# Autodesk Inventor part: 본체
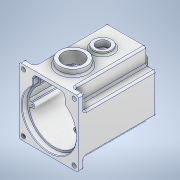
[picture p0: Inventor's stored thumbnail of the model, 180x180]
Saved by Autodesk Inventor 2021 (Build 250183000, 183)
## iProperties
Created: 2022-08
Part Number: 본체
Material: 알루미늄 6061
Document SubType Name: Modeling
Designer: Owner
Mass: 1404.24 g
Surface Area: 1170.95 cm^2
Volume: 520.089 cm^3
Density: 2.7 g/cm^3
Appearance: 알루미늄 - 평지
Author: Owner
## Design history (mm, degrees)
sketch "스케치1"
  geometry: L1 (-49, 55)-(49, 55); L2 (49, 55)-(49, -55); L3 (49, -55)-(-49, -55); L4 (-49, -55)-(-49, 55); L5 (-49, 55)-(49, -55); L6 (49, 55)-(-49, -55); 1 further point
  constraints: 12 end point, 2 midpoint, 2 parallel, 1 horizontal, 1 perpendicular
  dimensions: "d0" = 98 distance of L2.end L3.end; "d1" = 110 distance of L1.end L2.end
extrude "돌출1" new body sketch "스케치1" distance "d2" = 130; taper "d3" = 0 deg
sketch "스케치4"
  geometry: L1 (49, 55)-(-49, 55) reference; L2 (33, 55)-(49, 55); L3 (49, 55)-(49, 28); L4 (49, 28)-(33, 28); L5 (33, 28)-(33, 55); L6 (-49, -55)-(49, -55) reference; L7 (33, -38)-(49, -38); L8 (49, -38)-(49, -55); L9 (49, -55)-(33, -55); L10 (33, -55)-(33, -38); L11 (49, -55)-(49, 55) reference; 4 further points
  constraints: 16 end point, 4 parallel, 2 horizontal, 2 perpendicular, 2 point on line, 1 midpoint
  dimensions: "d9" = 16 distance of L3.end L4.end; "d10" = 16 distance of L7.start L7.end; "d11" = 27 distance of L4.end L2.start; "d12" = 17 distance of L9.end L7.start
extrude "돌출2" cut sketch "스케치4" distance "d13" = 120; taper "d14" = 0 deg
sketch "스케치5"
  geometry: L1 (-49, -55)-(49, -55) reference; L2 (-20, 48)-(20, 48); L3 (26, 42)-(26, 33.249); L4 (-26, 33.249)-(-26, 42); A1 r 45 centre (0, -5) between (-27.188, 30.859) and (27.188, 30.859); A2 r 3 centre (-29, 33.249) between (-27.188, 30.859) and (-26, 33.249); A3 r 3 centre (29, 33.249) between (26, 33.249) and (27.188, 30.859); A4 r 6 centre (-20, 42) between (-20, 48) and (-26, 42); A5 r 6 centre (20, 42) between (26, 42) and (20, 48); 5 further points
  constraints: 12 point on circle, 8 tangent, 6 end point, 6 point on line, 5 centre point, 2 equal radius, 1 horizontal, 1 parallel, 1 perpendicular, 1 vertical alignment
  dimensions: "d15" = 50 distance from line of A1.centre L1; "d16" = 45 radius of A1; "d17" = 52 distance between parallel lines of L3 L4; "d18" = 26 distance from line of A1.centre L3; "d19" = 53 distance from line of L2 A1.centre; "d20" = 3 radius of A2; "d23" = 6 radius of A4
extrude "돌출3" cut sketch "스케치5" distance "d21" = 9; taper "d22" = 0 deg
fillet "모깎기1" dims "d24" = 3
fillet "모깎기2" dims "d25" = 3
fillet "모깎기3" dims "d26" = 3
fillet "모깎기4" dims "d27" = 3
fillet "모깎기5" dims "d28" = 3
sketch "스케치6"
  geometry: L1 (-27, 33)-(27, 33); L2 (27, 33)-(27, -21); L3 (27, -21)-(-27, -21); L4 (-27, -21)-(-27, 33); L5 (-27, 33)-(27, -21); L6 (27, 33)-(-27, -21); L7 (-30, -55)-(30, -55) reference; 3 further points
  constraints: 12 end point, 4 midpoint, 2 parallel, 1 horizontal, 1 perpendicular, 1 vertical alignment
  dimensions: "d29" = 54 distance of L2.end L3.end; "d30" = 54 distance of L1.end L2.end; "d109" = 61 distance from line of point (0, 6) L7
extrude "돌출4" join sketch "스케치6" distance "d31" = 7; taper "d32" = 0 deg
fillet "모깎기6" dims "d33" = 3
fillet "모깎기7" dims "d34" = 3
sketch "스케치7"
  geometry: L1 (27, -18)-(27, 30) reference; L2 (24, 33)-(-24, 33) reference; 2 further points
  constraints: 1 coincident
  dimensions: "d110" = 27 distance from line of point (0, 6) L1; "d111" = 27 distance from line of point (0, 6) L2
hole "구멍1" sketch "스케치7" at (0, 6) diameter "d35" = 32; stored, may be unused: countersink angle "d39" = 90 deg, drill point angle "d41" = 0 deg; dims "d36" = 8, "d37" = 4, "d38" = 2, "d40" = 8.3
chamfer "모따기1" distance "d42" = 0.8; stored, may be unused: second distance "d43" = 2, angle "d44" = 30 deg
sketch "스케치8"
  geometry: L1 (92, 0)-(0, 0) reference; C1 r 15 at (46, 89); 2 further points
  constraints: 1 centre point, 1 midpoint, 1 vertical alignment
  dimensions: "d45" = 30 diameter of C1; "d46" = 89 distance from line of C1.centre L1
extrude "돌출5" join sketch "스케치8" distance "d47" = 5; taper "d48" = 0 deg
sketch "스케치9"
  geometry: L1 (92, 0)-(0, 0) reference; C1 r 22.5 at (46, 40); C2 r 15 at (46, 89) reference; 1 further point
  constraints: 1 centre point, 1 vertical alignment
  dimensions: "d49" = 45 diameter of C1; "d50" = 40 distance from line of C1.centre L1
extrude "돌출6" join sketch "스케치9" distance "d51" = 10; taper "d52" = 0 deg
fillet "모깎기8" dims "d53" = 3
sketch "스케치10"
  geometry: L1 (49, -52)-(49, 52) reference; L2 (-46, -55)-(46, -55) reference; 5 further points
  constraints: 2 horizontal alignment, 2 vertical alignment
  dimensions: "d54" = 7 distance from line of point (42, -48) L1; "d55" = 7 distance from line of point (42, -48) L2; "d56" = 96 distance of point (42, 48) point (42, -48); "d57" = 84 distance of point (-42, -48) point (42, -48)
hole "구멍2" sketch "스케치10" at (42, -48), (-42, -48), (-42, 48), (42, 48) diameter "d58" = 7; stored, may be unused: countersink angle "d62" = 90 deg, drill point angle "d64" = 0 deg; dims "d59" = 8, "d60" = 4, "d61" = 2, "d63" = 10
sketch "스케치11"
  geometry: L1 (-130, 104)-(-130, 83) reference; L2 (-13, 107)-(-127, 107) reference; 2 further points
  constraints: 1 other
  dimensions: "d65" = 65 distance from line of point (-65, 47) L1; "d66" = 60 distance from line of point (-65, 47) L2
feature "엠보싱1" sketch "스케치11" dims "d9" = 16, "d11" = 27, "d67" = 0.5, "d68" = 0
sketch "스케치13"
  geometry: C1 r 16 at (0, 0) reference; 2 further points
  constraints: 1 coincident
hole "구멍3" sketch "스케치13" at (0, 0) diameter "d71" = 28; stored, may be unused: countersink angle "d75" = 90 deg, drill point angle "d77" = 0 deg; dims "d72" = 8, "d73" = 4, "d74" = 2, "d76" = 10
fillet "모깎기9" dims "d78" = 0.3
sketch "스케치14"
  geometry: L1 (-20, 48)-(20, 48) reference; L2 (-26, 33.249)-(-26, 42) reference; L3 (26, 42)-(26, 33.249) reference; L4 (-23, 33.249)-(-23, 42); L5 (-20, 45)-(20, 45); L6 (23, 42)-(23, 33.249); L7 (-70.297, -5)-(83.266, -5); L8 (-46, -55)-(46, -55) reference; L9 (35.777, -1)-(41.809, -1); L10 (-41.809, -1)-(-35.777, -1); L11 (-41.809, -9)-(-35.777, -9); L12 (35.777, -9)-(41.809, -9); C1 r 14 at (0, 6) reference; A1 r 6 centre (-20, 42) between (-20, 48) and (-26, 42) reference; A2 r 3 centre (-29, 33.249) between (-27.188, 30.859) and (-26, 33.249) reference; A3 r 45 centre (0, -5) between (-27.188, 30.859) and (27.188, 30.859) reference; A4 r 3 centre (29, 33.249) between (26, 33.249) and (27.188, 30.859) reference; A5 r 6 centre (20, 42) between (26, 42) and (20, 48) reference; A6 r 6 centre (-29, 33.249) between (-25.375, 28.468) and (-23, 33.249); A7 r 3 centre (-20, 42) between (-20, 45) and (-23, 42); A8 r 3 centre (20, 42) between (23, 42) and (20, 45); A9 r 6 centre (29, 33.249) between (23, 33.249) and (25.375, 28.468); A10 r 36 centre (0, -5) between (-36, -5) and (36, -5); A11 r 4 centre (-36, -5) between (-36, -9) and (-36, -1); A12 r 4 centre (36, -5) between (36, -1) and (36, -9); A13 r 42 centre (0, -5) between (-25.375, 28.468) and (-41.809, -1); A14 r 42 centre (0, -5) between (-41.809, -9) and (41.809, -9); A15 r 42 centre (0, -5) between (41.809, -1) and (25.375, 28.468); 1 further point
  constraints: 24 point on circle, 16 end point, 10 centre point, 6 point on line, 5 horizontal, 4 tangent, 1 coincident, 6 other
  dimensions: "d89" = 50 distance between parallel lines of L7 L8; "d90" = 72 diameter of A10; "d91" = 8 diameter of A11; "d92" = 8 diameter of A12; "d93" = 42 radius of A15; "d94" = 42 radius of A14; "d95" = 42 radius of A13; "d96" = 6 radius of A6
extrude "돌출7" cut sketch "스케치14" distance "d80" = 112; taper "d81" = 0 deg
fillet "모깎기10" dims "d97" = 3
fillet "모깎기11" dims "d98" = 3
chamfer "모따기2" distance "d99" = 1; stored, may be unused: second distance "d100" = 2, angle "d101" = 30 deg
sketch "스케치16"
  geometry: A1 r 4 centre (-36, -5) between (-36, -9) and (-36, -1) reference; A2 r 4 centre (36, -5) between (36, -1) and (36, -9) reference; 3 further points
  constraints: 2 coincident
hole "구멍5" sketch "스케치16" at (-36, -5), (36, -5) diameter "d102" = 3.242; stored, may be unused: countersink angle "d106" = 90 deg, drill point angle "d108" = 118 deg; dims "d103" = 7, "d104" = 4, "d105" = 2, "d107" = 9
sketch "스케치17"
  geometry: C1 r 15 at (23, -80) reference; 1 further point
hole "구멍6" sketch "스케치17" at (23, -80) diameter "d112" = 20; stored, may be unused: countersink angle "d116" = 90 deg, drill point angle "d118" = 0 deg; dims "d113" = 7, "d114" = 30, "d115" = 5, "d117" = 20
sketch "스케치18"
  geometry: C1 r 22.5 at (0, 0) reference; 2 further points
  constraints: 1 coincident
hole "구멍7" sketch "스케치18" at (0, 0) diameter "d119" = 33.376; stored, may be unused: countersink angle "d123" = 90 deg, drill point angle "d125" = 0 deg; dims "d120" = 70, "d121" = 30, "d122" = 5, "d124" = 77.3
sketch "스케치19"
  geometry: L1 (-46, -55)-(46, -55) reference; C1 r 17.5 at (0, 6); C2 r 11 at (0, -25); A1 r 21 centre (0, 6) between (8.978, -12.984) and (-8.978, -12.984); A2 r 15 centre (0, -25) between (-8.978, -12.984) and (8.978, -12.984); 1 further point
  constraints: 4 centre point, 4 point on circle, 3 vertical alignment, 2 coincident
  dimensions: "d126" = 61 distance from line of A1.centre L1; "d127" = 42 diameter of A1; "d128" = 30 diameter of A2; "d129" = 35 diameter of C1; "d130" = 22 diameter of C2; "d131" = 31 distance of A2.centre A1.centre
extrude "돌출8" join sketch "스케치19" distance "d132" = 7; taper "d133" = 0 deg
sketch "스케치20"
  geometry: C1 r 11 at (0, 0) reference; 2 further points
  constraints: 1 coincident
hole "구멍8" sketch "스케치20" at (0, 0) diameter "d134" = 19; stored, may be unused: countersink angle "d138" = 90 deg, drill point angle "d140" = 0 deg; dims "d135" = 70, "d136" = 30, "d137" = 5, "d139" = 3
fillet "모깎기12" dims "d141" = 3
fillet "모깎기13" dims "d142" = 3
chamfer "모따기3" distance "d143" = 1; stored, may be unused: second distance "d144" = 2, angle "d145" = 30 deg
fillet "모깎기14" dims "d146" = 3
sketch "스케치21"
  geometry: C1 r 18.5 at (0, 0) reference; 2 further points
  constraints: 1 coincident
hole "구멍9" sketch "스케치21" at (0, 0) diameter "d147" = 35; stored, may be unused: countersink angle "d151" = 90 deg, drill point angle "d153" = 0 deg; dims "d148" = 70, "d149" = 30, "d150" = 5, "d152" = 3
chamfer "모따기4" distance "d154" = 1; stored, may be unused: second distance "d155" = 2, angle "d156" = 30 deg
fillet "모깎기17" dims "d159" = 0.3
fillet "모깎기18" dims "d160" = 0.3
node "솔리드1"
mirror "미러1"
node "투영된 루프1"
node "투영된 루프2"
feature "A9D066F2-1C7D-4E18-AEED-F7BC21143FA4" dims "d35" = 32, "d36" = 8, "d37" = 4, "d38" = 2, "d39" = 90 deg, "d40" = 8.3, "d41" = 0
other parameters: "d79" = 3
